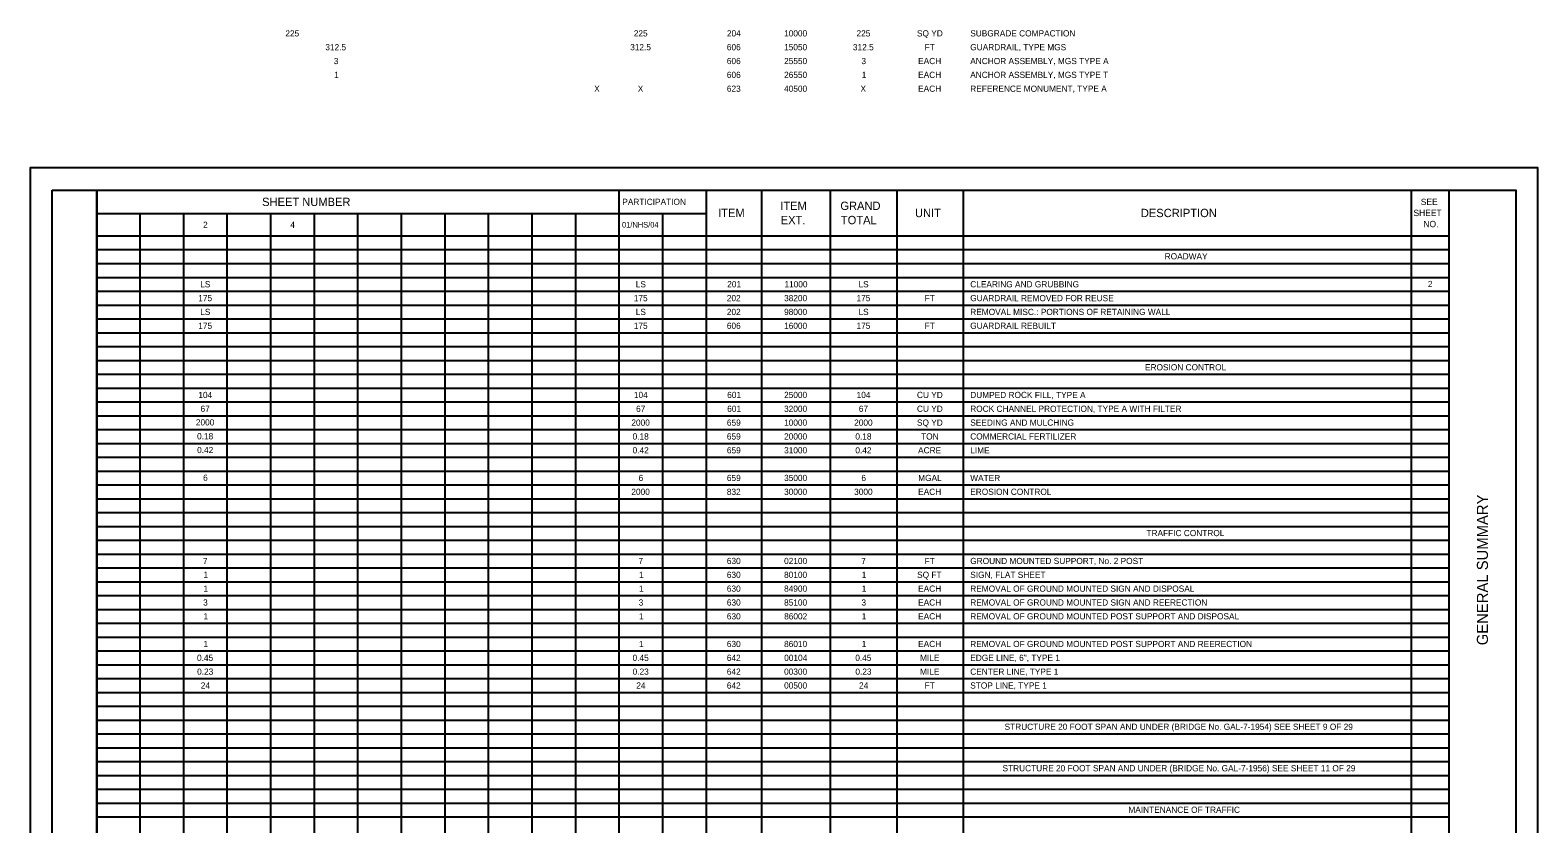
# Model space of a CAD drawing. Extents: x 0 to 34, y -10.8 to 25.1.
# Drawn here: x 0 to 34, y 7.21 to 25.11 of the extents above; entities that cross this region are included whole.
import ezdxf

# ---------------------------------------------------------------- set-up
doc = ezdxf.new("R2010")
doc.units = 0
for name, color, linetype in [('SH_Border', 7, 'Continuous'), ('SH_Cut_Line', 7, 'Continuous'), ('SH_Data', 7, 'Continuous'), ('TX_P_1', 7, 'Continuous')]:
    doc.layers.add(name, color=color, linetype=linetype)

msp = doc.modelspace()

# ---------------------------------------------------------------- linework, layer by layer
at = {"layer": 'SH_Border'}
msp.add_line((32, 0.5), (32, 21.5), dxfattribs=at)
msp.add_line((32, 0.5), (32, 21.5), dxfattribs=at)
for points in [[(0.5, 21.5), (1.5, 21.5), (1.5, 0.5), (0.5, 0.5)], [(1.5, 21.5), (33.5, 21.5), (33.5, 0.5), (1.5, 0.5)]]:
    msp.add_lwpolyline(points, close=True, dxfattribs=at)
at = {"layer": 'SH_Cut_Line'}
msp.add_lwpolyline([(0, 0), (34, 0), (34, 22), (0, 22)], close=True, dxfattribs=at)
at = {"layer": 'SH_Data'}
for p, q in [((13.286, 0.5), (13.286, 21.5)), ((15.25, 0.5), (15.25, 21.5)), ((16.5, 0.5), (16.5, 21.5)), ((18.05, 0.5), (18.05, 21.5)), ((19.55, 0.5), (19.55, 21.5)), ((21.05, 0.5), (21.05, 21.5)), ((31.15, 0.5), (31.15, 21.5)), ((1.5, 20.968), (15.25, 20.968)), ((2.482, 0.5), (2.482, 20.968)), ((3.464, 0.5), (3.464, 20.968)), ((4.446, 0.5), (4.446, 20.968)), ((5.429, 0.5), (5.429, 20.968)), ((6.411, 0.5), (6.411, 20.968)), ((7.393, 0.5), (7.393, 20.968)), ((8.375, 0.5), (8.375, 20.968)), ((9.357, 0.5), (9.357, 20.968)), ((10.339, 0.5), (10.339, 20.968)), ((11.321, 0.5), (11.321, 20.968)), ((12.304, 0.5), (12.304, 20.968)), ((14.268, 0.5), (14.268, 20.968)), ((1.5, 20.468), (32, 20.468)), ((1.5, 20.156), (32, 20.156)), ((1.5, 19.844), (32, 19.844)), ((1.5, 19.532), (32, 19.532)), ((1.5, 19.22), (32, 19.22)), ((1.5, 18.908), (32, 18.908)), ((1.5, 18.596), (32, 18.596)), ((1.5, 18.284), (32, 18.284)), ((1.5, 17.972), (32, 17.972)), ((1.5, 17.66), (32, 17.66)), ((1.5, 17.348), (32, 17.348)), ((1.5, 17.036), (32, 17.036)), ((1.5, 16.724), (32, 16.724)), ((1.5, 16.412), (32, 16.412)), ((1.5, 16.1), (32, 16.1)), ((1.5, 15.788), (32, 15.788)), ((1.5, 15.476), (32, 15.476)), ((1.5, 15.164), (32, 15.164)), ((1.5, 14.852), (32, 14.852)), ((1.5, 14.54), (32, 14.54)), ((1.5, 14.228), (32, 14.228)), ((1.5, 13.916), (32, 13.916)), ((1.5, 13.604), (32, 13.604)), ((1.5, 13.292), (32, 13.292)), ((1.5, 12.98), (32, 12.98)), ((1.5, 12.668), (32, 12.668)), ((1.5, 12.356), (32, 12.356)), ((1.5, 12.044), (32, 12.044)), ((1.5, 11.732), (32, 11.732)), ((1.5, 11.42), (32, 11.42)), ((1.5, 11.108), (32, 11.108)), ((1.5, 10.796), (32, 10.796)), ((1.5, 10.484), (32, 10.484)), ((1.5, 10.172), (32, 10.172)), ((1.5, 9.86), (32, 9.86)), ((1.5, 9.548), (32, 9.548)), ((1.5, 9.236), (32, 9.236)), ((1.5, 8.924), (32, 8.924)), ((1.5, 8.612), (32, 8.612)), ((1.5, 8.3), (32, 8.3)), ((1.5, 7.988), (32, 7.988)), ((1.5, 7.676), (32, 7.676)), ((1.5, 7.364), (32, 7.364))]:
    msp.add_line(p, q, dxfattribs=at)

# ---------------------------------------------------------------- texts
for s, height, p in [('SHEET NUMBER', 0.1875, (5.231, 21.14)), ('PARTICIPATION', 0.14, (13.353, 21.164)), ('ITEM', 0.1875, (16.915, 21.051)), ('GRAND', 0.1875, (18.271, 21.051)), ('DESCRIPTION', 0.1875, (25.047, 20.89)), ('SEE', 0.1426, (31.36, 21.162)), ('ITEM', 0.1875, (15.515, 20.89)), ('EXT.', 0.1875, (16.926, 20.73)), ('TOTAL', 0.1875, (18.283, 20.73)), ('UNIT', 0.1875, (19.954, 20.89)), ('SHEET', 0.1426, (31.195, 20.913)), ('NO.', 0.1426, (31.419, 20.663))]:
    msp.add_text(s, height=height, dxfattribs=at).set_placement(p)
msp.add_text('GENERAL SUMMARY', height=0.25, rotation=90, dxfattribs=at).set_placement((32.875, 11.235))
at = {"layer": 'TX_P_1'}
for s, height, p in [('225', 0.14, (5.755, 24.964)), ('225', 0.14, (13.612, 24.964)), ('204', 0.14, (15.713, 24.964)), ('10000', 0.14, (17.002, 24.964)), ('225', 0.14, (18.635, 24.964)), ('SQ YD', 0.14, (19.998, 24.964)), ('SUBGRADE COMPACTION', 0.14, (21.2, 24.964)), ('312.5', 0.14, (6.656, 24.652)), ('3', 0.14, (6.847, 24.34)), ('312.5', 0.14, (13.531, 24.652)), ('606', 0.14, (15.711, 24.652)), ('606', 0.14, (15.711, 24.34)), ('25550', 0.14, (17.002, 24.34)), ('15050', 0.14, (17.002, 24.652)), ('312.5', 0.14, (18.554, 24.652)), ('3', 0.14, (18.746, 24.34)), ('EACH', 0.14, (20.025, 24.34)), ('FT', 0.14, (20.171, 24.652)), ('ANCHOR ASSEMBLY, MGS TYPE A', 0.14, (21.2, 24.34)), ('GUARDRAIL, TYPE MGS', 0.14, (21.2, 24.652)), ('1', 0.14, (6.855, 24.028)), ('606', 0.14, (15.711, 24.028)), ('26550', 0.14, (17.002, 24.028)), ('1', 0.14, (18.753, 24.028)), ('EACH', 0.14, (20.025, 24.028)), ('ANCHOR ASSEMBLY, MGS TYPE T', 0.14, (21.2, 24.028)), ('X', 0.14, (12.719, 23.716)), ('X', 0.14, (13.702, 23.716)), ('623', 0.14, (15.712, 23.716)), ('40500', 0.14, (17.002, 23.716)), ('X', 0.14, (18.725, 23.716)), ('EACH', 0.14, (20.025, 23.716)), ('REFERENCE MONUMENT, TYPE A', 0.14, (21.2, 23.716)), ('2', 0.14, (3.9, 20.648)), ('4', 0.14, (5.866, 20.648)), ('01/NHS/04', 0.126, (13.347, 20.655)), ('ROADWAY', 0.14, (25.585, 19.936)), ('LS', 0.14, (3.835, 19.306)), ('LS', 0.14, (13.657, 19.306)), ('201', 0.14, (15.719, 19.306)), ('11000', 0.14, (17.01, 19.306)), ('LS', 0.14, (18.68, 19.306)), ('CLEARING AND GRUBBING', 0.14, (21.2, 19.306)), ('2', 0.14, (31.52, 19.312)), ('175', 0.14, (3.791, 18.994)), ('175', 0.14, (13.612, 18.994)), ('202', 0.14, (15.711, 18.994)), ('38200', 0.14, (17.002, 18.994)), ('175', 0.14, (18.635, 18.994)), ('FT', 0.14, (20.171, 18.994)), ('GUARDRAIL REMOVED FOR REUSE', 0.14, (21.2, 18.994)), ('LS', 0.14, (3.835, 18.682)), ('LS', 0.14, (13.657, 18.682)), ('202', 0.14, (15.711, 18.682)), ('98000', 0.14, (17.002, 18.682)), ('LS', 0.14, (18.68, 18.682)), ('REMOVAL MISC.: PORTIONS OF RETAINING WALL', 0.14, (21.2, 18.682)), ('175', 0.14, (3.791, 18.37)), ('175', 0.14, (13.612, 18.37)), ('606', 0.14, (15.711, 18.37)), ('16000', 0.14, (17.002, 18.37)), ('175', 0.14, (18.635, 18.37)), ('FT', 0.14, (20.171, 18.37)), ('GUARDRAIL REBUILT', 0.14, (21.2, 18.37)), ('EROSION CONTROL', 0.14, (25.141, 17.434)), ('104', 0.14, (3.793, 16.81)), ('104', 0.14, (13.615, 16.81)), ('601', 0.14, (15.719, 16.81)), ('25000', 0.14, (17.002, 16.81)), ('104', 0.14, (18.638, 16.81)), ('CU YD', 0.14, (19.998, 16.81)), ('DUMPED ROCK FILL, TYPE A', 0.14, (21.2, 16.81)), ('2000', 0.14, (3.737, 16.192)), ('67', 0.14, (3.843, 16.498)), ('2000', 0.14, (13.558, 16.186)), ('67', 0.14, (13.664, 16.498)), ('659', 0.14, (15.712, 16.186)), ('601', 0.14, (15.719, 16.498)), ('32000', 0.14, (17.002, 16.498)), ('10000', 0.14, (17.002, 16.186)), ('2000', 0.14, (18.582, 16.186)), ('67', 0.14, (18.687, 16.498)), ('SQ YD', 0.14, (19.998, 16.186)), ('CU YD', 0.14, (19.998, 16.498)), ('SEEDING AND MULCHING', 0.14, (21.2, 16.186)), ('ROCK CHANNEL PROTECTION, TYPE A WITH FILTER', 0.14, (21.2, 16.498)), ('0.18', 0.14, (3.764, 15.88)), ('0.18', 0.14, (13.586, 15.874)), ('659', 0.14, (15.712, 15.874)), ('20000', 0.14, (17.002, 15.874)), ('0.18', 0.14, (18.609, 15.874)), ('TON', 0.14, (20.092, 15.874)), ('COMMERCIAL FERTILIZER', 0.14, (21.2, 15.874)), ('0.42', 0.14, (3.765, 15.568)), ('0.42', 0.14, (13.586, 15.562)), ('659', 0.14, (15.712, 15.562)), ('31000', 0.14, (17.002, 15.562)), ('0.42', 0.14, (18.609, 15.562)), ('ACRE', 0.14, (20.024, 15.562)), ('LIME', 0.14, (21.2, 15.562)), ('6', 0.14, (3.9, 14.944)), ('6', 0.14, (13.721, 14.938)), ('659', 0.14, (15.712, 14.938)), ('35000', 0.14, (17.002, 14.938)), ('6', 0.14, (18.745, 14.938)), ('MGAL', 0.14, (20.026, 14.938)), ('WATER', 0.14, (21.2, 14.938)), ('2000', 0.14, (13.558, 14.626)), ('832', 0.14, (15.711, 14.626)), ('30000', 0.14, (17.002, 14.626)), ('3000', 0.14, (18.582, 14.626)), ('EACH', 0.14, (20.025, 14.626)), ('EROSION CONTROL', 0.14, (21.2, 14.626)), ('TRAFFIC CONTROL', 0.14, (25.174, 13.696)), ('7', 0.14, (3.897, 13.066)), ('7', 0.14, (13.719, 13.066)), ('630', 0.14, (15.711, 13.066)), ('02100', 0.14, (17.002, 13.066)), ('7', 0.14, (18.742, 13.066)), ('FT', 0.14, (20.171, 13.066)), ('GROUND MOUNTED SUPPORT, No. 2 POST', 0.14, (21.2, 13.066)), ('1', 0.14, (3.909, 12.754)), ('1', 0.14, (3.909, 12.442)), ('1', 0.14, (13.73, 12.754)), ('1', 0.14, (13.73, 12.442)), ('630', 0.14, (15.711, 12.754)), ('630', 0.14, (15.711, 12.442)), ('80100', 0.14, (17.002, 12.754)), ('84900', 0.14, (17.002, 12.442)), ('1', 0.14, (18.753, 12.754)), ('1', 0.14, (18.753, 12.442)), ('SQ FT', 0.14, (20.002, 12.754)), ('EACH', 0.14, (20.025, 12.442)), ('SIGN, FLAT SHEET', 0.14, (21.2, 12.754)), ('REMOVAL OF GROUND MOUNTED SIGN AND DISPOSAL', 0.14, (21.2, 12.442)), ('3', 0.14, (3.901, 12.13)), ('3', 0.14, (13.722, 12.13)), ('630', 0.14, (15.711, 12.13)), ('85100', 0.14, (17.002, 12.13)), ('3', 0.14, (18.746, 12.13)), ('EACH', 0.14, (20.025, 12.13)), ('REMOVAL OF GROUND MOUNTED SIGN AND REERECTION', 0.14, (21.2, 12.13)), ('1', 0.14, (3.909, 11.818)), ('1', 0.14, (13.73, 11.818)), ('630', 0.14, (15.711, 11.818)), ('86002', 0.14, (17.003, 11.818)), ('1', 0.14, (18.753, 11.818)), ('EACH', 0.14, (20.025, 11.818)), ('REMOVAL OF GROUND MOUNTED POST SUPPORT AND DISPOSAL', 0.14, (21.2, 11.818)), ('1', 0.14, (3.909, 11.194)), ('1', 0.14, (13.73, 11.194)), ('630', 0.14, (15.711, 11.194)), ('86010', 0.14, (17.002, 11.194)), ('1', 0.14, (18.753, 11.194)), ('EACH', 0.14, (20.025, 11.194)), ('REMOVAL OF GROUND MOUNTED POST SUPPORT AND REERECTION', 0.14, (21.2, 11.194)), ('0.45', 0.14, (3.763, 10.882)), ('0.45', 0.14, (13.585, 10.882)), ('642', 0.14, (15.711, 10.882)), ('00104', 0.14, (17.004, 10.882)), ('0.45', 0.14, (18.608, 10.882)), ('MILE', 0.14, (20.067, 10.882)), ('EDGE LINE, 6", TYPE 1', 0.14, (21.2, 10.882)), ('0.23', 0.14, (3.765, 10.57)), ('0.23', 0.14, (13.586, 10.57)), ('642', 0.14, (15.711, 10.57)), ('00300', 0.14, (17.002, 10.57)), ('0.23', 0.14, (18.61, 10.57)), ('MILE', 0.14, (20.067, 10.57)), ('CENTER LINE, TYPE 1', 0.14, (21.2, 10.57)), ('24', 0.14, (3.848, 10.258)), ('24', 0.14, (13.669, 10.258)), ('642', 0.14, (15.711, 10.258)), ('00500', 0.14, (17.002, 10.258)), ('24', 0.14, (18.692, 10.258)), ('FT', 0.14, (20.171, 10.258)), ('STOP LINE, TYPE 1', 0.14, (21.2, 10.258)), ('STRUCTURE 20 FOOT SPAN AND UNDER (BRIDGE No. GAL-7-1954) SEE SHEET 9 OF 29', 0.14, (21.975, 9.328)), ('STRUCTURE 20 FOOT SPAN AND UNDER (BRIDGE No. GAL-7-1956) SEE SHEET 11 OF 29', 0.14, (21.928, 8.392)), ('MAINTENANCE OF TRAFFIC', 0.14, (24.766, 7.456))]:
    msp.add_text(s, height=height, dxfattribs=at).set_placement(p)

doc.saveas('drawing.dxf')
